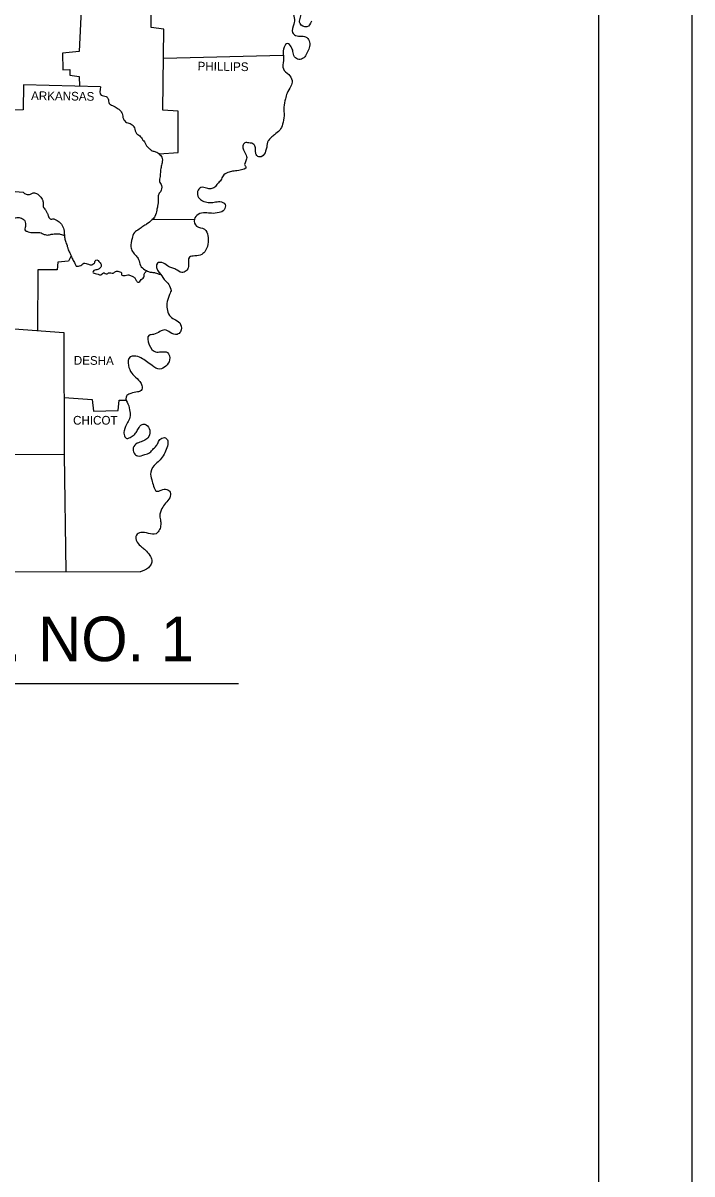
# Model space of a CAD drawing. Extents: x -0.25 to 1.92, y 0 to 0.95.
# Drawn here: x 1.2668 to 1.4167, y 0.4388 to 0.6965 of the extents above; entities that cross this region are included whole.
import ezdxf

# ---------------------------------------------------------------- set-up
doc = ezdxf.new("R2010")
doc.units = 0
for name, color, linetype in [('Default', 7, 'Continuous'), ('DSN_DRFT_Guideline-No-Plot', 7, 'Continuous'), ('SHET_Annotations', 7, 'Continuous'), ('SHET_Border-Lines', 7, 'Continuous'), ('SHET_Border-Text', 7, 'Continuous')]:
    doc.layers.add(name, color=color, linetype=linetype)

msp = doc.modelspace()

# ---------------------------------------------------------------- linework, layer by layer
at = {"layer": 'Default'}
for p, q in [((1.2958, 0.65251), (1.3052, 0.65256)), ((1.2958, 0.65251), (1.3052, 0.65256)), ((1.29742, 0.64027), (1.29756, 0.64027))]:
    msp.add_line(p, q, dxfattribs=at)
for points in [[(1.29727, 0.6672), (1.30154, 0.66747), (1.30152, 0.67671), (1.29814, 0.67697), (1.29833, 0.69507), (1.29547, 0.69548), (1.2954, 0.70767), (1.3345, 0.70793)], [(1.27994, 0.70259), (1.27939, 0.69009), (1.27566, 0.6897), (1.27574, 0.68599), (1.27727, 0.68604), (1.27729, 0.68477), (1.27934, 0.68454), (1.27942, 0.68231)], [(1.29826, 0.68863), (1.3251, 0.68928)], [(1.28417, 0.68218), (1.26689, 0.68267), (1.26679, 0.67704), (1.23188, 0.67691)], [(1.26084, 0.67702), (1.26049, 0.6591), (1.26679, 0.6586)], [(1.27755, 0.64437), (1.27698, 0.64315), (1.27457, 0.64291), (1.27444, 0.64125), (1.27008, 0.64125), (1.27003, 0.62762)], [(1.24595, 0.62831), (1.26282, 0.62816), (1.27597, 0.62717)], [(1.27597, 0.62717), (1.276, 0.59986), (1.27636, 0.57365)], [(1.12566, 0.61083), (1.12576, 0.5739), (1.29301, 0.57362)], [(1.27598, 0.61264), (1.28232, 0.61223), (1.28258, 0.60961), (1.28811, 0.60977), (1.28837, 0.61203), (1.29007, 0.61203)], [(1.24603, 0.59991), (1.276, 0.59994)]]:
    msp.add_lwpolyline(points, dxfattribs=at)
for points in [[(1.33142, 0.69688), (1.33038, 0.69559), (1.32885, 0.69639), (1.32885, 0.69748), (1.32906, 0.69865), (1.32851, 0.69937), (1.32755, 0.69906), (1.32755, 0.69764), (1.32745, 0.69623), (1.32716, 0.69432), (1.32784, 0.69369), (1.32927, 0.69354), (1.33035, 0.69323), (1.33098, 0.69221), (1.33093, 0.69092), (1.33041, 0.6897), (1.32968, 0.68869), (1.32857, 0.68832), (1.32763, 0.6889), (1.32727, 0.69011), (1.32688, 0.69113), (1.32608, 0.6919), (1.32527, 0.69107), (1.32509, 0.68947), (1.32514, 0.68809), (1.32512, 0.6862), (1.32631, 0.68498), (1.32706, 0.68358), (1.3268, 0.68231), (1.32595, 0.68078), (1.32558, 0.67948), (1.32525, 0.67767), (1.32527, 0.67572), (1.32493, 0.6738), (1.32431, 0.6725), (1.32312, 0.67147), (1.32234, 0.67079), (1.32172, 0.67009), (1.32138, 0.66872), (1.32115, 0.66778), (1.32029, 0.66662), (1.31959, 0.66654), (1.31905, 0.66701), (1.31889, 0.66778), (1.31887, 0.66854), (1.31853, 0.66931), (1.31739, 0.66965), (1.31648, 0.66963), (1.31606, 0.66898), (1.31664, 0.66719), (1.31689, 0.66605), (1.31653, 0.66449), (1.31671, 0.66431), (1.31511, 0.66345), (1.31376, 0.6633), (1.31267, 0.66299), (1.3116, 0.66229), (1.31111, 0.6613), (1.31039, 0.6605), (1.30976, 0.65972), (1.30888, 0.65936), (1.30792, 0.65951), (1.30665, 0.65967), (1.3059, 0.65876), (1.30613, 0.65744), (1.30701, 0.65666), (1.30831, 0.6563), (1.30963, 0.65637), (1.3109, 0.6565), (1.31207, 0.65586), (1.31184, 0.65464), (1.3107, 0.65404), (1.30901, 0.65388), (1.30764, 0.65399), (1.306, 0.65362), (1.3052, 0.65256), (1.30567, 0.65101), (1.30743, 0.65033), (1.30823, 0.64883), (1.30828, 0.64743), (1.30769, 0.64553), (1.30686, 0.64468), (1.30528, 0.64434), (1.30406, 0.64408), (1.30385, 0.64198), (1.30333, 0.64097), (1.30237, 0.64063), (1.301, 0.64133), (1.30017, 0.64164), (1.29916, 0.64211), (1.29791, 0.64286), (1.29693, 0.64273), (1.29721, 0.64071), (1.29729, 0.64063), (1.2984, 0.6391), (1.29947, 0.63793), (1.29999, 0.63653)], [(1.28417, 0.68218), (1.2843, 0.68031), (1.2854, 0.68003), (1.28585, 0.67953), (1.28608, 0.67848), (1.28686, 0.67803), (1.28791, 0.67739), (1.28855, 0.67693), (1.289, 0.6762), (1.28928, 0.67501), (1.29001, 0.67424), (1.29101, 0.67387), (1.29174, 0.67301), (1.2922, 0.67177), (1.29293, 0.67123), (1.29366, 0.67027), (1.29402, 0.66986), (1.29466, 0.66876), (1.2953, 0.66821), (1.29576, 0.66789), (1.29649, 0.66767), (1.2974, 0.66707), (1.29799, 0.66616), (1.29799, 0.66547), (1.29777, 0.66443), (1.29758, 0.66333), (1.29749, 0.6621), (1.2974, 0.661), (1.29781, 0.66009), (1.29758, 0.65872), (1.29713, 0.65799), (1.29708, 0.65699), (1.29694, 0.65548), (1.29676, 0.65461), (1.29635, 0.6532), (1.2958, 0.65251)], [(1.28417, 0.68218), (1.2843, 0.68031), (1.2854, 0.68003), (1.28585, 0.67953), (1.28608, 0.67848), (1.28686, 0.67803), (1.28791, 0.67739), (1.28855, 0.67693), (1.289, 0.6762), (1.28928, 0.67501), (1.29001, 0.67424), (1.29101, 0.67387), (1.29174, 0.67301), (1.2922, 0.67177), (1.29293, 0.67123), (1.29366, 0.67027), (1.29402, 0.66986), (1.29466, 0.66876), (1.2953, 0.66821), (1.29576, 0.66789), (1.29649, 0.66767), (1.2974, 0.66707), (1.29799, 0.66616), (1.29799, 0.66547), (1.29777, 0.66443), (1.29758, 0.66333), (1.29749, 0.6621), (1.2974, 0.661), (1.29781, 0.66009), (1.29758, 0.65872), (1.29713, 0.65799), (1.29708, 0.65699), (1.29694, 0.65548), (1.29676, 0.65461), (1.29635, 0.6532), (1.29576, 0.65247)], [(1.26679, 0.6586), (1.26752, 0.65814), (1.26848, 0.65819), (1.26907, 0.65845), (1.26962, 0.65842), (1.27027, 0.65801), (1.27076, 0.65749), (1.27107, 0.65707), (1.27128, 0.6564), (1.27128, 0.65583), (1.27151, 0.655), (1.2718, 0.65466), (1.27213, 0.65409), (1.27239, 0.65352), (1.2725, 0.65318), (1.27301, 0.65256), (1.27348, 0.65264), (1.27387, 0.65256), (1.27444, 0.65225), (1.27524, 0.65163), (1.2754, 0.65142), (1.27592, 0.65025), (1.27602, 0.64953), (1.2761, 0.64857), (1.27628, 0.64766), (1.27667, 0.64665), (1.27685, 0.64597), (1.27727, 0.64501), (1.27755, 0.64437), (1.27792, 0.64356), (1.27843, 0.64263), (1.27869, 0.64208), (1.27947, 0.64214), (1.27999, 0.64237), (1.28041, 0.64273), (1.28092, 0.64268), (1.28144, 0.6425), (1.28219, 0.64237), (1.28264, 0.64265), (1.2829, 0.64284), (1.28292, 0.64323), (1.28334, 0.64346), (1.2838, 0.64312), (1.28427, 0.6424), (1.28427, 0.64195), (1.28409, 0.64167), (1.28352, 0.64131), (1.28269, 0.64105), (1.28245, 0.64071), (1.28323, 0.64035), (1.28445, 0.64024), (1.28479, 0.64055), (1.28562, 0.64032), (1.28593, 0.64053), (1.28702, 0.6405), (1.28754, 0.64087), (1.28852, 0.64079), (1.28883, 0.64058), (1.28883, 0.64019), (1.28969, 0.63998), (1.29029, 0.64011), (1.29104, 0.63988), (1.29171, 0.63952), (1.29208, 0.63902), (1.29254, 0.63848), (1.29296, 0.63861), (1.29329, 0.63905), (1.29397, 0.63978), (1.29397, 0.64022), (1.29412, 0.64053), (1.29443, 0.6411)], [(1.26033, 0.65422), (1.26116, 0.65396), (1.26173, 0.65362), (1.26254, 0.65337), (1.263, 0.653), (1.26373, 0.65241), (1.26453, 0.65248), (1.2651, 0.65287), (1.2657, 0.65295), (1.26617, 0.6529), (1.26669, 0.65264), (1.26723, 0.6522), (1.26733, 0.65163), (1.26733, 0.65095), (1.26733, 0.64999), (1.26765, 0.64986), (1.26879, 0.64955), (1.26956, 0.6496), (1.27027, 0.6496), (1.27089, 0.64948), (1.27135, 0.64919), (1.27174, 0.64911), (1.27229, 0.64901), (1.27275, 0.64909), (1.27351, 0.64924), (1.27397, 0.64927), (1.27473, 0.64927), (1.27514, 0.64922), (1.27607, 0.64889)], [(1.29576, 0.65247), (1.29448, 0.65142), (1.29366, 0.65096), (1.29279, 0.65032), (1.29174, 0.64955), (1.29124, 0.64822), (1.29097, 0.6464), (1.29133, 0.6453), (1.29215, 0.64434), (1.2927, 0.64357), (1.29311, 0.6422), (1.29411, 0.64124), (1.29443, 0.6411)], [(1.29443, 0.6411), (1.2949, 0.64084), (1.29568, 0.64068), (1.29641, 0.64058), (1.29693, 0.64042), (1.29716, 0.64032), (1.29742, 0.64027)], [(1.29999, 0.63653), (1.29952, 0.63547), (1.29903, 0.63366), (1.29916, 0.6321), (1.29983, 0.63075), (1.30095, 0.63005), (1.30211, 0.62901), (1.30206, 0.62738), (1.30136, 0.62678), (1.29975, 0.6272), (1.29853, 0.62777), (1.29747, 0.62743), (1.29604, 0.62676), (1.29503, 0.6266), (1.29506, 0.62445), (1.29646, 0.62287), (1.2977, 0.62287), (1.29913, 0.62271), (1.29962, 0.62105), (1.29879, 0.6197), (1.29742, 0.61898), (1.29571, 0.61981), (1.29449, 0.62069), (1.29322, 0.62152), (1.29169, 0.62193), (1.2908, 0.62175), (1.29042, 0.61983), (1.29114, 0.61809), (1.29234, 0.61688), (1.29342, 0.61535), (1.29324, 0.6142), (1.29241, 0.61389), (1.29096, 0.61358), (1.29008, 0.61309), (1.28987, 0.61275), (1.29031, 0.6112), (1.29073, 0.60948), (1.29073, 0.60821), (1.29023, 0.60702), (1.28946, 0.60521), (1.28953, 0.60404), (1.29008, 0.60347), (1.29078, 0.60368), (1.29169, 0.6043), (1.29226, 0.60505), (1.29278, 0.60593), (1.29374, 0.60671), (1.2949, 0.60604), (1.29521, 0.60463), (1.29451, 0.60339), (1.29355, 0.60285), (1.29239, 0.6024), (1.29148, 0.60139), (1.29171, 0.6002), (1.29241, 0.59958), (1.2941, 0.59986), (1.29524, 0.60036), (1.29586, 0.60103), (1.29664, 0.60181), (1.29706, 0.60256), (1.29765, 0.60339), (1.29871, 0.60362), (1.29921, 0.60292), (1.29903, 0.60139), (1.29838, 0.59994), (1.29752, 0.59867), (1.29656, 0.59781), (1.2954, 0.59595), (1.29563, 0.59421), (1.29604, 0.59278), (1.29669, 0.59169), (1.29778, 0.59193), (1.29903, 0.59208), (1.29978, 0.59149), (1.29967, 0.59022), (1.29874, 0.58897), (1.29791, 0.5878), (1.29744, 0.58612), (1.29763, 0.58498), (1.29763, 0.58394), (1.29724, 0.5828), (1.29659, 0.58215), (1.29493, 0.58223), (1.29316, 0.58241), (1.29218, 0.58186), (1.29236, 0.58028), (1.29342, 0.57917), (1.29415, 0.57857), (1.29519, 0.57727), (1.29565, 0.57624), (1.2955, 0.57533), (1.29488, 0.57455), (1.29301, 0.57362)]]:
    msp.add_spline(points, degree=3, dxfattribs=at)
at = {"layer": 'DSN_DRFT_Guideline-No-Plot'}
msp.add_lwpolyline([(0, 0), (1.41667, 0), (1.41667, 0.91667), (0, 0.91667)], close=True, dxfattribs=at)
at = {"layer": 'SHET_Border-Lines'}
msp.add_lwpolyline([(0.02083, 0.02083), (1.39583, 0.02083), (1.39583, 0.89583), (0.02083, 0.89583)], close=True, dxfattribs=at)
at = {"layer": 'SHET_Border-Text'}
msp.add_line((1.15505, 0.54862), (1.31505, 0.54862), dxfattribs=at)

# ---------------------------------------------------------------- texts
at = {"layer": 'Default'}
for s, rotation, p in [('PHILLIPS', 359.217, (1.30589, 0.68586)), ('ARKANSAS', 359.2655, (1.26859, 0.67925)), ('DESHA', 359.2949, (1.27816, 0.62002))]:
    msp.add_text(s, height=0.001945, rotation=rotation, dxfattribs=at).set_placement(p)
msp.add_text('CHICOT', height=0.001945, dxfattribs=at).set_placement((1.27801, 0.60658))
at = {"layer": 'SHET_Annotations'}
msp.add_text('ARK. HWY. DIST. NO. 1', height=0.01, dxfattribs=at).set_placement((1.15874, 0.55362))

doc.saveas('drawing.dxf')
